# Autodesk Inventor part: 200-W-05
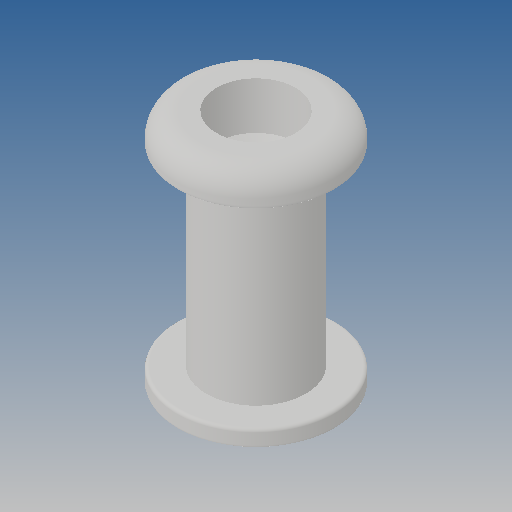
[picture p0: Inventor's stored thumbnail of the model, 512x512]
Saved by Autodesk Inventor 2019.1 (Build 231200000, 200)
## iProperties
Created: 2011-05
Part Number: 200-W-05
Material: Ogólny
Document SubType Name: Modeling
Designer: CADENGINEERING4
Density: 1 g/cm^3
Appearance: Domyślna
Author: CADENGINEERING4
Revision Number: ÈÎºÎ
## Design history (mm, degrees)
feature "Ðý×ª1"
node "Bryła1"
